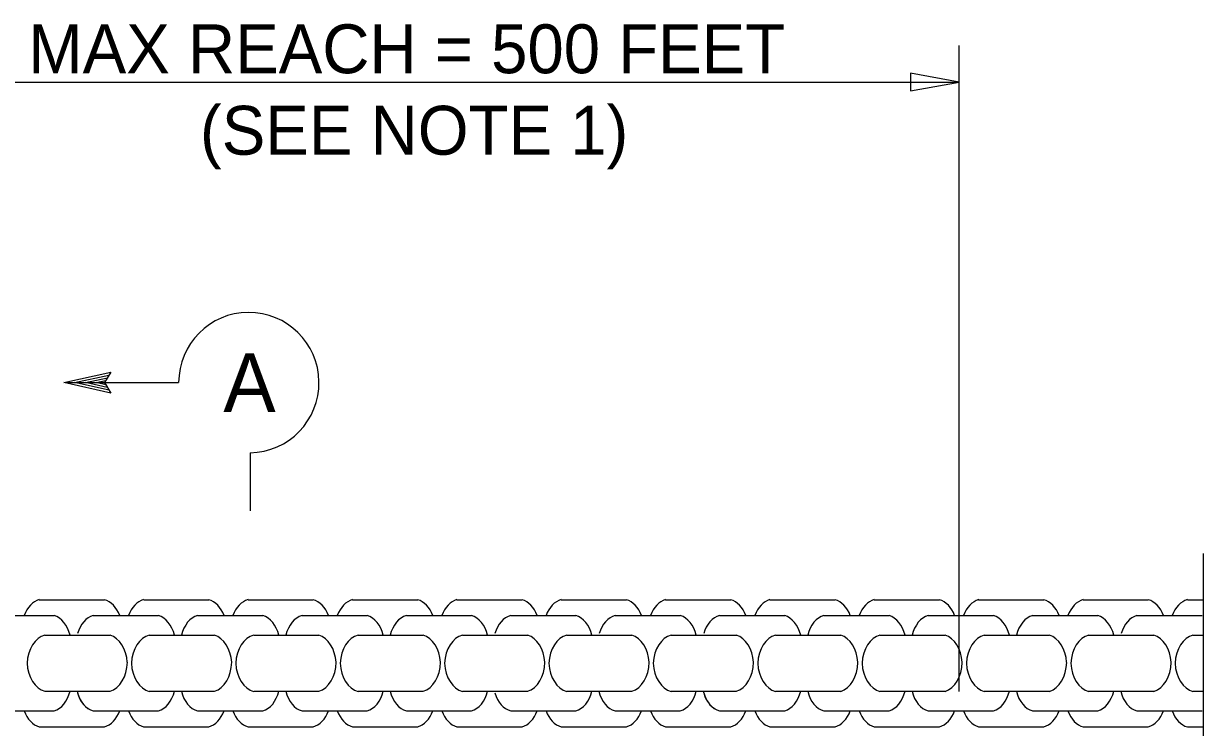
# Model space of a CAD drawing. Extents: x 6707406 to 6714471, y 1868570 to 1872341.
# Drawn here: x 6712507.4 to 6712652.3, y 1870380.7 to 1870467.1 of the extents above; entities that cross this region are included whole.
import ezdxf

# ---------------------------------------------------------------- set-up
doc = ezdxf.new("R2010")
doc.units = 0
for name, color, linetype in [('56 Stg 3 Anno', 7, 'Continuous'), ('57 Undefined', 7, 'Continuous'), ('C - SANDBAG', 7, 'Continuous'), ('Default', 7, 'Continuous'), ('G-SYMB', 7, 'Continuous')]:
    doc.layers.add(name, color=color, linetype=linetype)

# ---------------------------------------------------------------- blocks, each defined once
blk = doc.blocks.new('ARROW')
at = {"layer": 'Default'}
blk.add_lwpolyline([(-0.01042, -0.00183), (0, 0), (-0.01042, 0.00183)], close=True, dxfattribs=at)

msp = doc.modelspace()

# ---------------------------------------------------------------- linework, layer by layer
at = {"layer": '56 Stg 3 Anno'}
for p, q in [((6712512.33, 1870422.99), (6712518.1, 1870424.27)), ((6712513.67, 1870423), (6712517.87, 1870423.92)), ((6712518.1, 1870424.27), (6712517.33, 1870422.99)), ((6712518.1, 1870424.27), (6712518.1, 1870424.27)), ((6712518.1, 1870421.71), (6712512.33, 1870422.99)), ((6712512.33, 1870422.99), (6712512.33, 1870422.99)), ((6712512.51, 1870422.99), (6712526.44, 1870422.99)), ((6712517.89, 1870422.05), (6712513.66, 1870422.99)), ((6712514.99, 1870422.99), (6712517.7, 1870423.59)), ((6712517.66, 1870422.39), (6712514.99, 1870422.99)), ((6712516.31, 1870422.99), (6712517.47, 1870423.25)), ((6712517.49, 1870422.73), (6712516.31, 1870422.99)), ((6712517.33, 1870422.99), (6712518.1, 1870421.71)), ((6712518.1, 1870421.71), (6712518.1, 1870421.71)), ((6712535.22, 1870414.37), (6712535.22, 1870407.24))]:
    msp.add_line(p, q, dxfattribs=at)
msp.add_arc((6712535.06, 1870422.99), 8.62, 271.113, 179.9585, dxfattribs=at)
at = {"layer": 'C - SANDBAG'}
for p, q in [((6712509.33, 1870396.34), (6712517.33, 1870396.34)), ((6712522.15, 1870396.34), (6712530.15, 1870396.34)), ((6712522.15, 1870396.34), (6712530.15, 1870396.34)), ((6712534.97, 1870396.34), (6712542.97, 1870396.34)), ((6712547.79, 1870396.34), (6712555.8, 1870396.34)), ((6712560.61, 1870396.34), (6712568.62, 1870396.34)), ((6712573.42, 1870396.34), (6712581.43, 1870396.34)), ((6712586.24, 1870396.34), (6712594.25, 1870396.34)), ((6712599.06, 1870396.34), (6712607.07, 1870396.34)), ((6712599.06, 1870396.34), (6712607.07, 1870396.34)), ((6712611.88, 1870396.34), (6712619.89, 1870396.34)), ((6712624.7, 1870396.34), (6712632.71, 1870396.34)), ((6712637.52, 1870396.34), (6712645.53, 1870396.34)), ((6712650.33, 1870396.34), (6712652.3, 1870396.34)), ((6712503.13, 1870394.39), (6712511.14, 1870394.39)), ((6712515.95, 1870394.39), (6712523.96, 1870394.39)), ((6712515.95, 1870394.39), (6712523.96, 1870394.39)), ((6712528.77, 1870394.39), (6712536.78, 1870394.39)), ((6712541.6, 1870394.39), (6712549.6, 1870394.39)), ((6712554.42, 1870394.39), (6712562.42, 1870394.39)), ((6712567.23, 1870394.39), (6712575.23, 1870394.39)), ((6712580.05, 1870394.39), (6712588.05, 1870394.39)), ((6712592.87, 1870394.39), (6712600.88, 1870394.39)), ((6712592.87, 1870394.39), (6712600.88, 1870394.39)), ((6712605.69, 1870394.39), (6712613.7, 1870394.39)), ((6712618.51, 1870394.39), (6712626.52, 1870394.39)), ((6712631.33, 1870394.39), (6712639.34, 1870394.39)), ((6712644.14, 1870394.39), (6712652.15, 1870394.39)), ((6712510.02, 1870391.99), (6712518.02, 1870391.99)), ((6712522.84, 1870391.99), (6712530.84, 1870391.99)), ((6712522.84, 1870391.99), (6712530.84, 1870391.99)), ((6712535.66, 1870391.99), (6712543.66, 1870391.99)), ((6712548.48, 1870391.98), (6712556.48, 1870391.98)), ((6712561.3, 1870391.98), (6712569.31, 1870391.98)), ((6712574.11, 1870391.98), (6712582.12, 1870391.98)), ((6712586.93, 1870391.98), (6712594.94, 1870391.98)), ((6712599.75, 1870391.98), (6712607.76, 1870391.98)), ((6712599.75, 1870391.98), (6712607.76, 1870391.98)), ((6712612.57, 1870391.98), (6712620.58, 1870391.98)), ((6712625.39, 1870391.98), (6712633.4, 1870391.98)), ((6712638.21, 1870391.98), (6712646.22, 1870391.98)), ((6712651.02, 1870391.98), (6712652.3, 1870391.98)), ((6712510.02, 1870385.09), (6712518.02, 1870385.09)), ((6712522.84, 1870385.09), (6712530.84, 1870385.09)), ((6712522.84, 1870385.09), (6712530.84, 1870385.09)), ((6712535.66, 1870385.09), (6712543.66, 1870385.09)), ((6712548.48, 1870385.09), (6712556.48, 1870385.09)), ((6712561.3, 1870385.09), (6712569.31, 1870385.09)), ((6712574.11, 1870385.09), (6712582.12, 1870385.09)), ((6712586.93, 1870385.09), (6712594.94, 1870385.09)), ((6712599.75, 1870385.09), (6712607.76, 1870385.09)), ((6712599.75, 1870385.09), (6712607.76, 1870385.09)), ((6712612.57, 1870385.09), (6712620.58, 1870385.09)), ((6712625.39, 1870385.09), (6712633.4, 1870385.09)), ((6712638.21, 1870385.09), (6712646.22, 1870385.09)), ((6712651.02, 1870385.09), (6712652.3, 1870385.09)), ((6712503.13, 1870382.69), (6712511.14, 1870382.69)), ((6712515.95, 1870382.69), (6712523.96, 1870382.69)), ((6712515.95, 1870382.69), (6712523.96, 1870382.69)), ((6712528.77, 1870382.69), (6712536.78, 1870382.69)), ((6712541.6, 1870382.69), (6712549.6, 1870382.69)), ((6712554.42, 1870382.69), (6712562.42, 1870382.69)), ((6712567.23, 1870382.69), (6712575.23, 1870382.69)), ((6712580.05, 1870382.69), (6712588.05, 1870382.69)), ((6712592.87, 1870382.69), (6712600.88, 1870382.69)), ((6712592.87, 1870382.69), (6712600.88, 1870382.69)), ((6712605.69, 1870382.69), (6712613.7, 1870382.69)), ((6712618.51, 1870382.68), (6712626.52, 1870382.68)), ((6712631.33, 1870382.68), (6712639.34, 1870382.68)), ((6712644.14, 1870382.68), (6712652.15, 1870382.68)), ((6712509.33, 1870380.74), (6712517.33, 1870380.74)), ((6712522.15, 1870380.74), (6712530.15, 1870380.74)), ((6712522.15, 1870380.74), (6712530.15, 1870380.74)), ((6712534.97, 1870380.74), (6712542.97, 1870380.74)), ((6712547.79, 1870380.73), (6712555.8, 1870380.73)), ((6712560.61, 1870380.73), (6712568.62, 1870380.73)), ((6712573.42, 1870380.73), (6712581.43, 1870380.73)), ((6712586.24, 1870380.73), (6712594.25, 1870380.73)), ((6712599.06, 1870380.73), (6712607.07, 1870380.73)), ((6712599.06, 1870380.73), (6712607.07, 1870380.73)), ((6712611.88, 1870380.73), (6712619.89, 1870380.73)), ((6712624.7, 1870380.73), (6712632.71, 1870380.73)), ((6712637.52, 1870380.73), (6712645.53, 1870380.73)), ((6712650.33, 1870380.73), (6712652.3, 1870380.73))]:
    msp.add_line(p, q, dxfattribs=at)
for centre, major_axis, ratio, start_param, end_param in [((6712509.85, 1870392.66), (0.06, -3.75), 0.711359, 3.317588, 4.221159), ((6712516.85, 1870392.66), (0.06, -3.75), 0.71077, 2.038051, 2.935943), ((6712522.67, 1870392.66), (0.06, -3.75), 0.711359, 3.317588, 4.221159), ((6712522.67, 1870392.66), (0.06, -3.75), 0.711359, 3.317588, 4.221159), ((6712529.67, 1870392.66), (0.06, -3.75), 0.71077, 2.038051, 2.935943), ((6712529.67, 1870392.66), (0.06, -3.75), 0.71077, 2.038051, 2.935943), ((6712535.49, 1870392.66), (0.06, -3.75), 0.711359, 3.317588, 4.221159), ((6712542.49, 1870392.66), (0.06, -3.75), 0.71077, 2.038051, 2.935943), ((6712548.31, 1870392.66), (0.06, -3.75), 0.711359, 3.317588, 4.221159), ((6712555.31, 1870392.66), (0.06, -3.75), 0.71077, 2.038051, 2.935943), ((6712561.14, 1870392.66), (0.06, -3.75), 0.711359, 3.317588, 4.221159), ((6712568.13, 1870392.66), (0.06, -3.75), 0.71077, 2.038177, 2.935943), ((6712573.95, 1870392.66), (0.06, -3.75), 0.711359, 3.317588, 4.221159), ((6712580.94, 1870392.66), (0.06, -3.75), 0.71077, 2.038051, 2.935943), ((6712586.77, 1870392.66), (0.06, -3.75), 0.711359, 3.317588, 4.221159), ((6712593.76, 1870392.66), (0.06, -3.75), 0.71077, 2.038051, 2.935943), ((6712599.59, 1870392.66), (0.06, -3.75), 0.711359, 3.317588, 4.221159), ((6712599.59, 1870392.66), (0.06, -3.75), 0.711359, 3.317588, 4.221159), ((6712606.58, 1870392.66), (0.06, -3.75), 0.71077, 2.038051, 2.935943), ((6712606.58, 1870392.66), (0.06, -3.75), 0.71077, 2.038051, 2.935943), ((6712612.41, 1870392.66), (0.06, -3.75), 0.711359, 3.317588, 4.221159), ((6712619.4, 1870392.66), (0.06, -3.75), 0.71077, 2.038051, 2.935943), ((6712625.23, 1870392.66), (0.06, -3.75), 0.711359, 3.317588, 4.221159), ((6712632.23, 1870392.66), (0.06, -3.75), 0.71077, 2.038051, 2.935943), ((6712638.05, 1870392.66), (0.06, -3.75), 0.711359, 3.317588, 4.221159), ((6712645.05, 1870392.66), (0.06, -3.75), 0.71077, 2.038177, 2.935943), ((6712650.86, 1870392.66), (0.06, -3.75), 0.711359, 3.317588, 4.221159), ((6712510.6, 1870390.72), (0, -3.75), 0.71077, 1.915159, 2.935943), ((6712516.48, 1870390.71), (0.06, -3.75), 0.711359, 3.317588, 4.29466), ((6712516.48, 1870390.71), (0.06, -3.75), 0.711359, 3.317588, 4.29466), ((6712523.42, 1870390.72), (0, -3.75), 0.71077, 1.915159, 2.935943), ((6712523.42, 1870390.72), (0, -3.75), 0.71077, 1.915159, 2.935943), ((6712529.3, 1870390.71), (0.06, -3.75), 0.711359, 3.317588, 4.353284), ((6712536.24, 1870390.72), (0, -3.75), 0.71077, 1.915159, 2.935943), ((6712542.12, 1870390.71), (0.06, -3.75), 0.711359, 3.317588, 4.353284), ((6712549.06, 1870390.72), (0, -3.75), 0.71077, 1.915159, 2.935943), ((6712554.94, 1870390.71), (0.06, -3.75), 0.711359, 3.317588, 4.353284), ((6712561.88, 1870390.72), (0, -3.75), 0.71077, 1.915159, 2.935943), ((6712567.75, 1870390.71), (0.06, -3.75), 0.711359, 3.317588, 4.29466), ((6712574.69, 1870390.72), (0, -3.75), 0.71077, 1.915159, 2.935943), ((6712580.57, 1870390.71), (0.06, -3.75), 0.711359, 3.317588, 4.29466), ((6712587.51, 1870390.72), (0, -3.75), 0.71077, 1.915159, 2.935943), ((6712593.39, 1870390.71), (0.06, -3.75), 0.711359, 3.317588, 4.29466), ((6712593.39, 1870390.71), (0.06, -3.75), 0.711359, 3.317588, 4.29466), ((6712600.33, 1870390.72), (0, -3.75), 0.71077, 1.915159, 2.935943), ((6712600.33, 1870390.72), (0, -3.75), 0.71077, 1.915159, 2.935943), ((6712606.22, 1870390.71), (0.06, -3.75), 0.711359, 3.317588, 4.353284), ((6712613.15, 1870390.72), (0, -3.75), 0.71077, 1.915159, 2.935943), ((6712619.04, 1870390.71), (0.06, -3.75), 0.711359, 3.317588, 4.353284), ((6712625.97, 1870390.72), (0, -3.75), 0.71077, 1.915159, 2.935943), ((6712631.86, 1870390.71), (0.06, -3.75), 0.711359, 3.317588, 4.353284), ((6712638.79, 1870390.72), (0, -3.75), 0.71077, 1.915159, 2.935943), ((6712644.67, 1870390.71), (0.06, -3.75), 0.711359, 3.317588, 4.29466), ((6712510.48, 1870388.3), (0, -3.75), 0.711359, 3.317588, 4.646994), ((6712517.48, 1870388.31), (0, -3.75), 0.71077, 1.662213, 2.935943), ((6712523.3, 1870388.29), (0, -3.75), 0.711359, 3.317588, 4.646994), ((6712523.3, 1870388.29), (0, -3.75), 0.711359, 3.317588, 4.646994), ((6712530.3, 1870388.31), (0, -3.75), 0.71077, 1.662213, 2.935943), ((6712530.3, 1870388.31), (0, -3.75), 0.71077, 1.662213, 2.935943), ((6712536.12, 1870388.29), (0, -3.75), 0.711359, 3.317588, 4.646994), ((6712543.12, 1870388.31), (0, -3.75), 0.71077, 1.662213, 2.935943), ((6712548.94, 1870388.29), (0, -3.75), 0.711359, 3.317588, 4.646994), ((6712555.94, 1870388.31), (0, -3.75), 0.71077, 1.662213, 2.935943), ((6712561.77, 1870388.29), (0, -3.75), 0.711359, 3.317588, 4.646994), ((6712568.76, 1870388.31), (0, -3.75), 0.71077, 1.662213, 2.935943), ((6712574.58, 1870388.29), (0, -3.75), 0.711359, 3.317588, 4.646994), ((6712581.57, 1870388.31), (0, -3.75), 0.71077, 1.662213, 2.935943), ((6712587.4, 1870388.29), (0, -3.75), 0.711359, 3.317588, 4.646994), ((6712594.39, 1870388.31), (0, -3.75), 0.71077, 1.662213, 2.935943), ((6712600.22, 1870388.29), (0, -3.75), 0.711359, 3.317588, 4.646994), ((6712600.22, 1870388.29), (0, -3.75), 0.711359, 3.317588, 4.646994), ((6712607.21, 1870388.31), (0, -3.75), 0.71077, 1.662213, 2.935943), ((6712607.21, 1870388.31), (0, -3.75), 0.71077, 1.662213, 2.935943), ((6712613.04, 1870388.29), (0, -3.75), 0.711359, 3.317588, 4.646994), ((6712620.03, 1870388.31), (0, -3.75), 0.71077, 1.662213, 2.935943), ((6712625.86, 1870388.29), (0, -3.75), 0.711359, 3.317588, 4.646994), ((6712632.85, 1870388.31), (0, -3.75), 0.71077, 1.662213, 2.935943), ((6712638.68, 1870388.29), (0, -3.75), 0.711359, 3.317588, 4.646994), ((6712645.68, 1870388.31), (0, -3.75), 0.71077, 1.662213, 2.935943), ((6712651.49, 1870388.29), (0, -3.75), 0.711359, 3.317588, 4.646994), ((6712510.48, 1870388.79), (0, 3.75), 0.711359, 1.636191, 2.965597), ((6712517.48, 1870388.77), (0, 3.75), 0.71077, 3.347242, 4.682592), ((6712523.3, 1870388.78), (0, 3.75), 0.711359, 1.636191, 2.965597), ((6712523.3, 1870388.78), (0, 3.75), 0.711359, 1.636191, 2.965597), ((6712530.3, 1870388.77), (0, 3.75), 0.71077, 3.347242, 4.682592), ((6712530.3, 1870388.77), (0, 3.75), 0.71077, 3.347242, 4.682592), ((6712536.12, 1870388.78), (0, 3.75), 0.711359, 1.636191, 2.965597), ((6712543.12, 1870388.77), (0, 3.75), 0.71077, 3.347242, 4.682592), ((6712548.94, 1870388.78), (0, 3.75), 0.711359, 1.636191, 2.965597), ((6712555.94, 1870388.77), (0, 3.75), 0.71077, 3.347242, 4.682592), ((6712561.77, 1870388.78), (0, 3.75), 0.711359, 1.636191, 2.965597), ((6712568.76, 1870388.77), (0, 3.75), 0.71077, 3.347242, 4.682592), ((6712574.58, 1870388.78), (0, 3.75), 0.711359, 1.636191, 2.965597), ((6712581.57, 1870388.77), (0, 3.75), 0.71077, 3.347242, 4.682592), ((6712587.4, 1870388.78), (0, 3.75), 0.711359, 1.636191, 2.965597), ((6712594.39, 1870388.77), (0, 3.75), 0.71077, 3.347242, 4.682592), ((6712600.22, 1870388.78), (0, 3.75), 0.711359, 1.636191, 2.965597), ((6712600.22, 1870388.78), (0, 3.75), 0.711359, 1.636191, 2.965597), ((6712607.21, 1870388.76), (0, 3.75), 0.71077, 3.347242, 4.682592), ((6712607.21, 1870388.76), (0, 3.75), 0.71077, 3.347242, 4.682592), ((6712613.04, 1870388.78), (0, 3.75), 0.711359, 1.636191, 2.965597), ((6712620.03, 1870388.76), (0, 3.75), 0.71077, 3.347242, 4.682592), ((6712625.86, 1870388.78), (0, 3.75), 0.711359, 1.636191, 2.965597), ((6712632.85, 1870388.76), (0, 3.75), 0.71077, 3.347242, 4.682592), ((6712638.68, 1870388.78), (0, 3.75), 0.711359, 1.636191, 2.965597), ((6712645.68, 1870388.76), (0, 3.75), 0.71077, 3.347242, 4.682592), ((6712651.49, 1870388.78), (0, 3.75), 0.711359, 1.636191, 2.965597), ((6712510.6, 1870386.36), (0, 3.75), 0.71077, 3.347242, 4.368026), ((6712516.48, 1870386.37), (0.06, 3.75), 0.711359, 1.929645, 2.965597), ((6712516.48, 1870386.37), (0.06, 3.75), 0.711359, 1.988526, 2.965597), ((6712523.42, 1870386.36), (0, 3.75), 0.71077, 3.347242, 4.368026), ((6712523.42, 1870386.36), (0, 3.75), 0.71077, 3.347242, 4.368026), ((6712529.3, 1870386.37), (0.06, 3.75), 0.711359, 1.929645, 2.965597), ((6712536.24, 1870386.36), (0, 3.75), 0.71077, 3.347242, 4.368026), ((6712542.12, 1870386.37), (0.06, 3.75), 0.711359, 1.929645, 2.965597), ((6712549.06, 1870386.36), (0, 3.75), 0.71077, 3.347242, 4.368026), ((6712554.94, 1870386.37), (0.06, 3.75), 0.711359, 1.929645, 2.965597), ((6712561.88, 1870386.36), (0, 3.75), 0.71077, 3.347242, 4.368026), ((6712567.75, 1870386.37), (0.06, 3.75), 0.711359, 1.988526, 2.965597), ((6712574.69, 1870386.36), (0, 3.75), 0.71077, 3.347242, 4.368026), ((6712580.57, 1870386.37), (0.06, 3.75), 0.711359, 1.929645, 2.965597), ((6712587.51, 1870386.36), (0, 3.75), 0.71077, 3.347242, 4.368026), ((6712593.39, 1870386.37), (0.06, 3.75), 0.711359, 1.929645, 2.965597), ((6712593.39, 1870386.37), (0.06, 3.75), 0.711359, 1.988526, 2.965597), ((6712600.33, 1870386.36), (0, 3.75), 0.71077, 3.347242, 4.368026), ((6712600.33, 1870386.36), (0, 3.75), 0.71077, 3.347242, 4.368026), ((6712606.22, 1870386.37), (0.06, 3.75), 0.711359, 1.929645, 2.965597), ((6712613.15, 1870386.36), (0, 3.75), 0.71077, 3.347242, 4.368026), ((6712619.04, 1870386.37), (0.06, 3.75), 0.711359, 1.929645, 2.965597), ((6712625.97, 1870386.36), (0, 3.75), 0.71077, 3.347242, 4.368026), ((6712631.86, 1870386.37), (0.06, 3.75), 0.711359, 1.929645, 2.965597), ((6712638.79, 1870386.36), (0, 3.75), 0.71077, 3.347242, 4.368026), ((6712644.67, 1870386.37), (0.06, 3.75), 0.711359, 1.929764, 2.965597), ((6712509.85, 1870384.42), (0.06, 3.75), 0.711359, 2.062027, 2.965597), ((6712516.85, 1870384.42), (0.06, 3.75), 0.71077, 3.347242, 4.244863), ((6712522.67, 1870384.42), (0.06, 3.75), 0.711359, 2.062027, 2.965597), ((6712522.67, 1870384.42), (0.06, 3.75), 0.711359, 2.062027, 2.965597), ((6712529.67, 1870384.42), (0.06, 3.75), 0.71077, 3.347242, 4.244863), ((6712529.67, 1870384.42), (0.06, 3.75), 0.71077, 3.347242, 4.244863), ((6712535.49, 1870384.42), (0.06, 3.75), 0.711359, 2.062027, 2.965597), ((6712542.49, 1870384.42), (0.06, 3.75), 0.71077, 3.347242, 4.244863), ((6712548.31, 1870384.42), (0.06, 3.75), 0.711359, 2.062027, 2.965597), ((6712555.31, 1870384.42), (0.06, 3.75), 0.71077, 3.347242, 4.244863), ((6712561.14, 1870384.42), (0.06, 3.75), 0.711359, 2.062027, 2.965597), ((6712568.13, 1870384.42), (0.06, 3.75), 0.71077, 3.347242, 4.244988), ((6712573.95, 1870384.42), (0.06, 3.75), 0.711359, 2.062027, 2.965597), ((6712580.94, 1870384.42), (0.06, 3.75), 0.71077, 3.347242, 4.244863), ((6712586.77, 1870384.42), (0.06, 3.75), 0.711359, 2.062027, 2.965597), ((6712593.76, 1870384.41), (0.06, 3.75), 0.71077, 3.347242, 4.244863), ((6712599.59, 1870384.42), (0.06, 3.75), 0.711359, 2.062027, 2.965597), ((6712599.59, 1870384.42), (0.06, 3.75), 0.711359, 2.062027, 2.965597), ((6712606.58, 1870384.41), (0.06, 3.75), 0.71077, 3.347242, 4.244863), ((6712606.58, 1870384.41), (0.06, 3.75), 0.71077, 3.347242, 4.244863), ((6712612.41, 1870384.42), (0.06, 3.75), 0.711359, 2.062027, 2.965597), ((6712619.4, 1870384.41), (0.06, 3.75), 0.71077, 3.347242, 4.244863), ((6712625.23, 1870384.42), (0.06, 3.75), 0.711359, 2.062027, 2.965597), ((6712632.23, 1870384.41), (0.06, 3.75), 0.71077, 3.347242, 4.244863), ((6712638.05, 1870384.41), (0.06, 3.75), 0.711359, 2.062027, 2.965597), ((6712645.05, 1870384.41), (0.06, 3.75), 0.71077, 3.347242, 4.244988), ((6712650.86, 1870384.41), (0.06, 3.75), 0.711359, 2.062027, 2.965597)]:
    msp.add_ellipse(centre, major_axis=major_axis, ratio=ratio, start_param=start_param, end_param=end_param, dxfattribs=at)
at = {"layer": 'G-SYMB'}
for p, q in [((6712622.31, 1870385.08), (6712622.31, 1870464.39)), ((6712494.09, 1870459.89), (6712622.31, 1870459.89)), ((6712652.3, 1870376.31), (6712652.3, 1870402.01))]:
    msp.add_line(p, q, dxfattribs=at)

# ---------------------------------------------------------------- block references
at = {"layer": 'G-SYMB', "xscale": 575.9999999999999, "yscale": 589.090909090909}
msp.add_blockref('ARROW', (6712622.31, 1870459.89), dxfattribs=at)

# ---------------------------------------------------------------- texts
at = {"layer": '57 Undefined'}
msp.add_text('A', height=7.21, dxfattribs=at).set_placement((6712531.93, 1870419.38))
at = {"layer": 'G-SYMB'}
for s, p in [('MAX REACH = 500 FEET', (6712507.97, 1870460.97)), ('(SEE NOTE 1)', (6712529.06, 1870450.97))]:
    msp.add_text(s, height=6, dxfattribs=at).set_placement(p)

doc.saveas('drawing.dxf')
